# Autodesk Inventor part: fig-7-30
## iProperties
Shininess: 77.0
Length Units: 11269
Angle Units: 11279
Time Units: 11290
Mass Units: 11283
Length Display Precision: 3
Angle Display Precision: 2
Created: 2002-01
Part Number: fig-7-30
Document SubType Name: Modeling
Designer: CADSoft
Density: 1 g/cm^3
Density: 0.0
Volumn: 0.0
Area: 0.0
PropertySet Name: Model Information
Control State: 0
Master: False
Checked Out: False
Author: CADSoft
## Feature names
1. Extrusion2
2. Coil6
